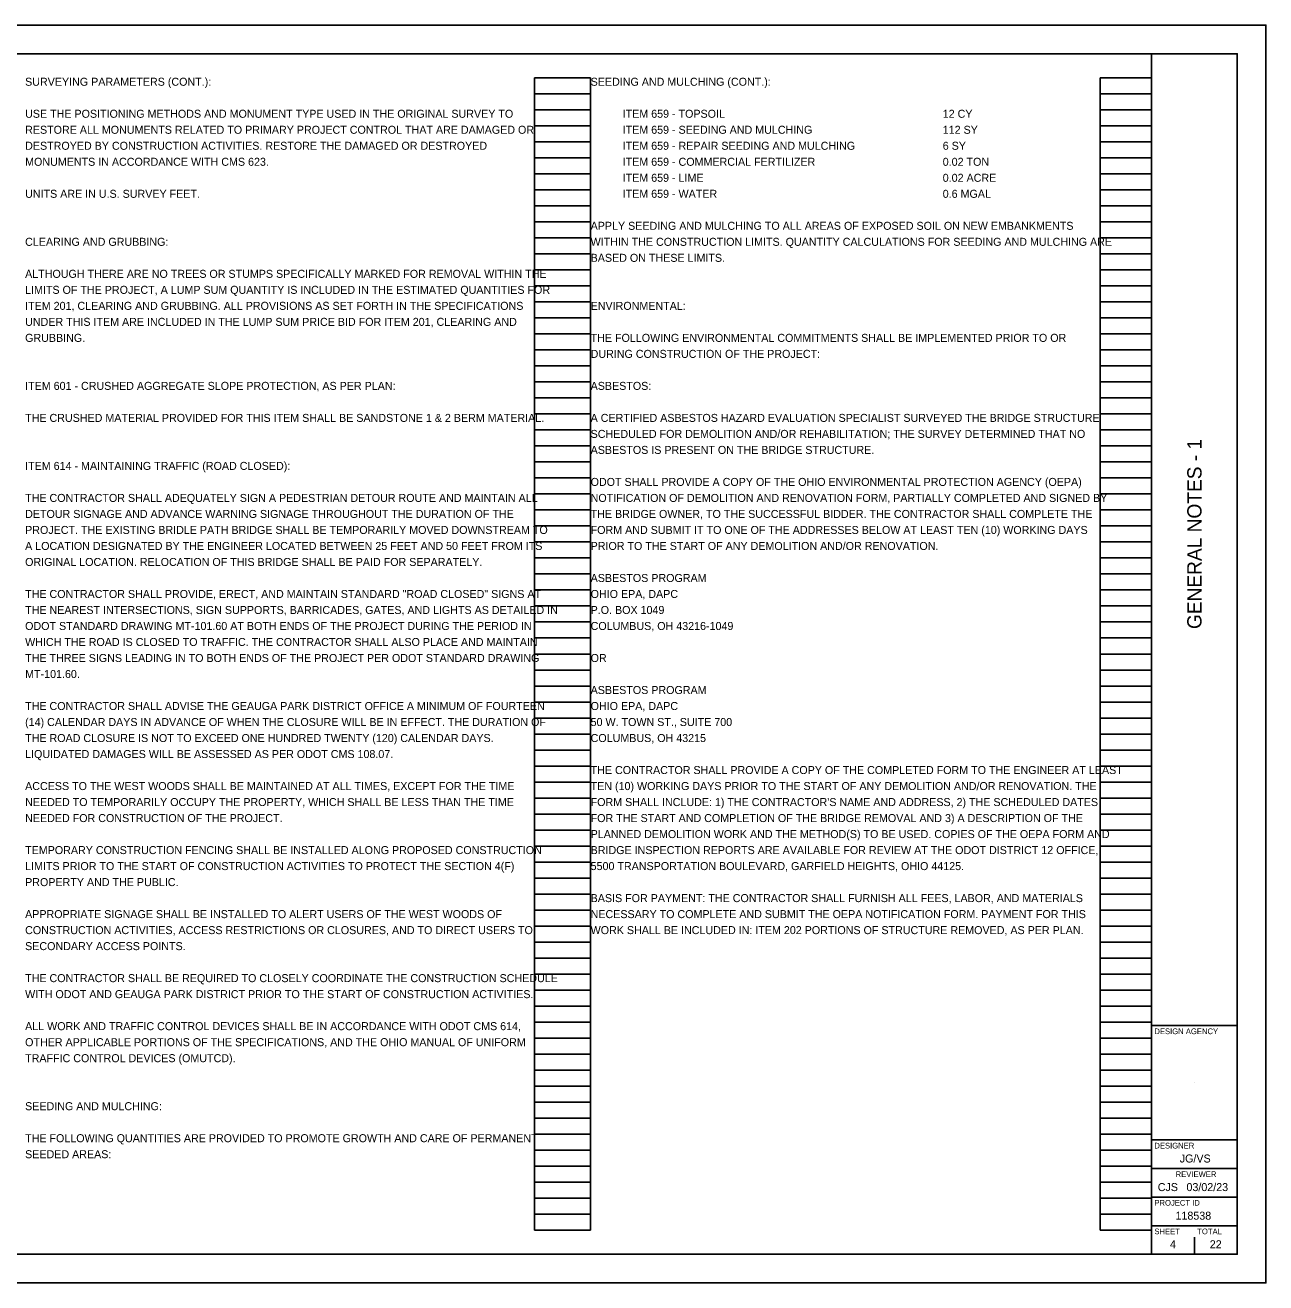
# Model space of a CAD drawing. Extents: x 0 to 34, y -0.1 to 22.
# Drawn here: x 12.29 to 34, y 0 to 22 of the extents above; entities that cross this region are included whole.
import ezdxf

# ---------------------------------------------------------------- set-up
doc = ezdxf.new("R2010")
doc.units = 0
for name, color, linetype in [('SH_Border', 7, 'Continuous'), ('SH_Cut_Line', 7, 'Continuous'), ('SH_Data', 7, 'Continuous'), ('SH_Text', 7, 'Continuous')]:
    doc.layers.add(name, color=color, linetype=linetype)

msp = doc.modelspace()

# ---------------------------------------------------------------- linework, layer by layer
at = {"layer": 'SH_Border'}
for p, q in [((32, 0.5), (32, 21.5)), ((32, 4.5), (33.5, 4.5)), ((32, 2.5), (33.5, 2.5)), ((32, 2), (33.5, 2)), ((32, 1.5), (33.5, 1.5)), ((32, 1), (33.5, 1))]:
    msp.add_line(p, q, dxfattribs=at)
msp.add_lwpolyline([(1.5, 21.5), (33.5, 21.5), (33.5, 0.5), (1.5, 0.5)], close=True, dxfattribs=at)
at = {"layer": 'SH_Cut_Line'}
msp.add_lwpolyline([(0, 0), (34, 0), (34, 22), (0, 22)], close=True, dxfattribs=at)
at = {"layer": 'SH_Data'}
for p, q in [((21.207, 0.92), (21.207, 21.08)), ((21.207, 21.08), (22.187, 21.08)), ((22.187, 0.92), (22.187, 21.08)), ((31.1, 0.92), (31.1, 21.08)), ((31.1, 21.08), (32, 21.08)), ((32, 0.92), (32, 21.08)), ((21.207, 20.8), (22.187, 20.8)), ((31.1, 20.8), (32, 20.8)), ((21.207, 20.52), (22.187, 20.52)), ((31.1, 20.52), (32, 20.52)), ((21.207, 20.24), (22.187, 20.24)), ((31.1, 20.24), (32, 20.24)), ((21.207, 19.96), (22.187, 19.96)), ((31.1, 19.96), (32, 19.96)), ((21.207, 19.68), (22.187, 19.68)), ((31.1, 19.68), (32, 19.68)), ((21.207, 19.4), (22.187, 19.4)), ((31.1, 19.4), (32, 19.4)), ((21.207, 19.12), (22.187, 19.12)), ((31.1, 19.12), (32, 19.12)), ((21.207, 18.84), (22.187, 18.84)), ((31.1, 18.84), (32, 18.84)), ((21.207, 18.56), (22.187, 18.56)), ((31.1, 18.56), (32, 18.56)), ((21.207, 18.28), (22.187, 18.28)), ((31.1, 18.28), (32, 18.28)), ((21.207, 18), (22.187, 18)), ((31.1, 18), (32, 18)), ((21.207, 17.72), (22.187, 17.72)), ((31.1, 17.72), (32, 17.72)), ((21.207, 17.44), (22.187, 17.44)), ((31.1, 17.44), (32, 17.44)), ((21.207, 17.16), (22.187, 17.16)), ((31.1, 17.16), (32, 17.16)), ((21.207, 16.88), (22.187, 16.88)), ((31.1, 16.88), (32, 16.88)), ((21.207, 16.6), (22.187, 16.6)), ((31.1, 16.6), (32, 16.6)), ((21.207, 16.32), (22.187, 16.32)), ((31.1, 16.32), (32, 16.32)), ((21.207, 16.04), (22.187, 16.04)), ((31.1, 16.04), (32, 16.04)), ((21.207, 15.76), (22.187, 15.76)), ((31.1, 15.76), (32, 15.76)), ((21.207, 15.48), (22.187, 15.48)), ((31.1, 15.48), (32, 15.48)), ((21.207, 15.2), (22.187, 15.2)), ((31.1, 15.2), (32, 15.2)), ((21.207, 14.92), (22.187, 14.92)), ((31.1, 14.92), (32, 14.92)), ((21.207, 14.64), (22.187, 14.64)), ((31.1, 14.64), (32, 14.64)), ((21.207, 14.36), (22.187, 14.36)), ((31.1, 14.36), (32, 14.36)), ((21.207, 14.08), (22.187, 14.08)), ((31.1, 14.08), (32, 14.08)), ((21.207, 13.8), (22.187, 13.8)), ((31.1, 13.8), (32, 13.8)), ((21.207, 13.52), (22.187, 13.52)), ((31.1, 13.52), (32, 13.52)), ((21.207, 13.24), (22.187, 13.24)), ((31.1, 13.24), (32, 13.24)), ((21.207, 12.96), (22.187, 12.96)), ((31.1, 12.96), (32, 12.96)), ((21.207, 12.68), (22.187, 12.68)), ((31.1, 12.68), (32, 12.68)), ((21.207, 12.4), (22.187, 12.4)), ((31.1, 12.4), (32, 12.4)), ((21.207, 12.12), (22.187, 12.12)), ((31.1, 12.12), (32, 12.12)), ((21.207, 11.84), (22.187, 11.84)), ((31.1, 11.84), (32, 11.84)), ((21.207, 11.56), (22.187, 11.56)), ((31.1, 11.56), (32, 11.56)), ((21.207, 11.28), (22.187, 11.28)), ((31.1, 11.28), (32, 11.28)), ((21.207, 11), (22.187, 11)), ((31.1, 11), (32, 11)), ((21.207, 10.72), (22.187, 10.72)), ((31.1, 10.72), (32, 10.72)), ((21.207, 10.44), (22.187, 10.44)), ((31.1, 10.44), (32, 10.44)), ((21.207, 10.16), (22.187, 10.16)), ((31.1, 10.16), (32, 10.16)), ((21.207, 9.88), (22.187, 9.88)), ((31.1, 9.88), (32, 9.88)), ((21.207, 9.6), (22.187, 9.6)), ((31.1, 9.6), (32, 9.6)), ((21.207, 9.32), (22.187, 9.32)), ((31.1, 9.32), (32, 9.32)), ((21.207, 9.04), (22.187, 9.04)), ((31.1, 9.04), (32, 9.04)), ((21.207, 8.76), (22.187, 8.76)), ((31.1, 8.76), (32, 8.76)), ((21.207, 8.48), (22.187, 8.48)), ((31.1, 8.48), (32, 8.48)), ((21.207, 8.2), (22.187, 8.2)), ((31.1, 8.2), (32, 8.2)), ((21.207, 7.92), (22.187, 7.92)), ((31.1, 7.92), (32, 7.92)), ((21.207, 7.64), (22.187, 7.64)), ((31.1, 7.64), (32, 7.64)), ((21.207, 7.36), (22.187, 7.36)), ((31.1, 7.36), (32, 7.36)), ((21.207, 7.08), (22.187, 7.08)), ((31.1, 7.08), (32, 7.08)), ((21.207, 6.8), (22.187, 6.8)), ((31.1, 6.8), (32, 6.8)), ((21.207, 6.52), (22.187, 6.52)), ((31.1, 6.52), (32, 6.52)), ((21.207, 6.24), (22.187, 6.24)), ((31.1, 6.24), (32, 6.24)), ((21.207, 5.96), (22.187, 5.96)), ((31.1, 5.96), (32, 5.96)), ((21.207, 5.68), (22.187, 5.68)), ((31.1, 5.68), (32, 5.68)), ((21.207, 5.4), (22.187, 5.4)), ((31.1, 5.4), (32, 5.4)), ((21.207, 5.12), (22.187, 5.12)), ((31.1, 5.12), (32, 5.12)), ((21.207, 4.84), (22.187, 4.84)), ((31.1, 4.84), (32, 4.84)), ((21.207, 4.56), (22.187, 4.56)), ((31.1, 4.56), (32, 4.56)), ((21.207, 4.28), (22.187, 4.28)), ((31.1, 4.28), (32, 4.28)), ((21.207, 4), (22.187, 4)), ((31.1, 4), (32, 4)), ((21.207, 3.72), (22.187, 3.72)), ((31.1, 3.72), (32, 3.72)), ((21.207, 3.44), (22.187, 3.44)), ((31.1, 3.44), (32, 3.44)), ((32.75, 3.5), (32.75, 3.5)), ((21.207, 3.16), (22.187, 3.16)), ((31.1, 3.16), (32, 3.16)), ((21.207, 2.88), (22.187, 2.88)), ((31.1, 2.88), (32, 2.88)), ((21.207, 2.6), (22.187, 2.6)), ((31.1, 2.6), (32, 2.6)), ((21.207, 2.32), (22.187, 2.32)), ((31.1, 2.32), (32, 2.32)), ((21.207, 2.04), (22.187, 2.04)), ((31.1, 2.04), (32, 2.04)), ((21.207, 1.76), (22.187, 1.76)), ((31.1, 1.76), (32, 1.76)), ((21.207, 1.48), (22.187, 1.48)), ((31.1, 1.48), (32, 1.48)), ((21.207, 1.2), (22.187, 1.2)), ((31.1, 1.2), (32, 1.2)), ((21.207, 0.92), (22.187, 0.92)), ((31.1, 0.92), (32, 0.92)), ((32.375, 0.675), (32.375, 0.675)), ((32.75, 0.5), (32.75, 0.8))]:
    msp.add_line(p, q, dxfattribs=at)

# ---------------------------------------------------------------- texts
msp.add_text('GENERAL NOTES - 1', height=0.25, rotation=90, dxfattribs=at).set_placement((32.875, 11.437))
for s, height, p in [('DESIGN AGENCY', 0.1, (32.05, 4.35)), ('DESIGNER', 0.1, (32.05, 2.35)), ('JG/VS', 0.14, (32.494, 2.105)), ('REVIEWER', 0.1, (32.422, 1.85)), ('CJS', 0.14, (32.109, 1.605)), ('03/02/23', 0.14, (32.611, 1.605)), ('PROJECT ID', 0.1, (32.05, 1.35)), ('118538', 0.14, (32.419, 1.105)), ('SHEET', 0.1, (32.05, 0.85)), ('TOTAL', 0.1, (32.8, 0.85)), ('4', 0.14, (32.322, 0.605)), ('22', 0.14, (33.019, 0.605))]:
    msp.add_text(s, height=height, dxfattribs=at).set_placement(p)
at = {"layer": 'SH_Text'}
for s, p in [('SURVEYING PARAMETERS (CONT.):', (12.293, 20.94)), ('SEEDING AND MULCHING (CONT.):', (22.187, 20.94)), ('USE THE POSITIONING METHODS AND MONUMENT TYPE USED IN THE ORIGINAL SURVEY TO ', (12.293, 20.38)), ('ITEM 659 - TOPSOIL', (22.747, 20.38)), ('12 CY', (28.347, 20.38)), ('RESTORE ALL MONUMENTS RELATED TO PRIMARY PROJECT CONTROL THAT ARE DAMAGED OR', (12.293, 20.1)), ('ITEM 659 - SEEDING AND MULCHING', (22.747, 20.1)), ('112 SY', (28.347, 20.1)), ('DESTROYED BY CONSTRUCTION ACTIVITIES. RESTORE THE DAMAGED OR DESTROYED ', (12.293, 19.82)), ('ITEM 659 - REPAIR SEEDING AND MULCHING', (22.747, 19.82)), ('6 SY', (28.347, 19.82)), ('MONUMENTS IN ACCORDANCE WITH CMS 623.', (12.293, 19.54)), ('ITEM 659 - COMMERCIAL FERTILIZER', (22.747, 19.54)), ('0.02 TON', (28.347, 19.54)), ('ITEM 659 - LIME', (22.747, 19.26)), ('0.02 ACRE', (28.347, 19.26)), ('UNITS ARE IN U.S. SURVEY FEET.', (12.293, 18.98)), ('ITEM 659 - WATER', (22.747, 18.98)), ('0.6 MGAL', (28.347, 18.98)), ('APPLY SEEDING AND MULCHING TO ALL AREAS OF EXPOSED SOIL ON NEW EMBANKMENTS ', (22.187, 18.42)), ('CLEARING AND GRUBBING:', (12.293, 18.14)), ('WITHIN THE CONSTRUCTION LIMITS. QUANTITY CALCULATIONS FOR SEEDING AND MULCHING ARE ', (22.187, 18.14)), ('BASED ON THESE LIMITS.', (22.187, 17.86)), ('ALTHOUGH THERE ARE NO TREES OR STUMPS SPECIFICALLY MARKED FOR REMOVAL WITHIN THE ', (12.293, 17.58)), ('LIMITS OF THE PROJECT, A LUMP SUM QUANTITY IS INCLUDED IN THE ESTIMATED QUANTITIES FOR ', (12.293, 17.3)), ('ITEM 201, CLEARING AND GRUBBING. ALL PROVISIONS AS SET FORTH IN THE SPECIFICATIONS ', (12.293, 17.02)), ('ENVIRONMENTAL:', (22.187, 17.02)), ('UNDER THIS ITEM ARE INCLUDED IN THE LUMP SUM PRICE BID FOR ITEM 201, CLEARING AND ', (12.293, 16.74)), ('GRUBBING.', (12.293, 16.46)), ('THE FOLLOWING ENVIRONMENTAL COMMITMENTS SHALL BE IMPLEMENTED PRIOR TO OR ', (22.187, 16.46)), ('DURING CONSTRUCTION OF THE PROJECT:', (22.187, 16.18)), ('ITEM 601 - CRUSHED AGGREGATE SLOPE PROTECTION, AS PER PLAN:', (12.293, 15.62)), ('ASBESTOS:', (22.187, 15.62)), ('THE CRUSHED MATERIAL PROVIDED FOR THIS ITEM SHALL BE SANDSTONE 1 & 2 BERM MATERIAL.', (12.293, 15.06)), ('A CERTIFIED ASBESTOS HAZARD EVALUATION SPECIALIST SURVEYED THE BRIDGE STRUCTURE ', (22.187, 15.06)), ('SCHEDULED FOR DEMOLITION AND/OR REHABILITATION; THE SURVEY DETERMINED THAT NO ', (22.187, 14.78)), ('ASBESTOS IS PRESENT ON THE BRIDGE STRUCTURE.', (22.187, 14.5)), ('ITEM 614 - MAINTAINING TRAFFIC (ROAD CLOSED):', (12.293, 14.22)), ('ODOT SHALL PROVIDE A COPY OF THE OHIO ENVIRONMENTAL PROTECTION AGENCY (OEPA) ', (22.187, 13.94)), ('THE CONTRACTOR SHALL ADEQUATELY SIGN A PEDESTRIAN DETOUR ROUTE AND MAINTAIN ALL ', (12.293, 13.66)), ('NOTIFICATION OF DEMOLITION AND RENOVATION FORM, PARTIALLY COMPLETED AND SIGNED BY ', (22.187, 13.66)), ('DETOUR SIGNAGE AND ADVANCE WARNING SIGNAGE THROUGHOUT THE DURATION OF THE ', (12.293, 13.38)), ('THE BRIDGE OWNER, TO THE SUCCESSFUL BIDDER. THE CONTRACTOR SHALL COMPLETE THE ', (22.187, 13.38)), ('PROJECT. THE EXISTING BRIDLE PATH BRIDGE SHALL BE TEMPORARILY MOVED DOWNSTREAM TO ', (12.293, 13.1)), ('FORM AND SUBMIT IT TO ONE OF THE ADDRESSES BELOW AT LEAST TEN (10) WORKING DAYS ', (22.187, 13.1)), ('A LOCATION DESIGNATED BY THE ENGINEER LOCATED BETWEEN 25 FEET AND 50 FEET FROM ITS ', (12.293, 12.82)), ('PRIOR TO THE START OF ANY DEMOLITION AND/OR RENOVATION.', (22.187, 12.82)), ('ORIGINAL LOCATION. RELOCATION OF THIS BRIDGE SHALL BE PAID FOR SEPARATELY.', (12.293, 12.54)), ('ASBESTOS PROGRAM', (22.187, 12.26)), ('THE CONTRACTOR SHALL PROVIDE, ERECT, AND MAINTAIN STANDARD "ROAD CLOSED" SIGNS AT ', (12.293, 11.98)), ('OHIO EPA, DAPC', (22.187, 11.98)), ('THE NEAREST INTERSECTIONS, SIGN SUPPORTS, BARRICADES, GATES, AND LIGHTS AS DETAILED IN ', (12.293, 11.7)), ('P.O. BOX 1049', (22.187, 11.7)), ('ODOT STANDARD DRAWING MT-101.60 AT BOTH ENDS OF THE PROJECT DURING THE PERIOD IN ', (12.293, 11.42)), ('COLUMBUS, OH 43216-1049', (22.187, 11.42)), ('WHICH THE ROAD IS CLOSED TO TRAFFIC. THE CONTRACTOR SHALL ALSO PLACE AND MAINTAIN ', (12.293, 11.14)), ('THE THREE SIGNS LEADING IN TO BOTH ENDS OF THE PROJECT PER ODOT STANDARD DRAWING ', (12.293, 10.86)), ('OR', (22.187, 10.86)), ('MT-101.60.', (12.293, 10.58)), ('ASBESTOS PROGRAM', (22.187, 10.3)), ('THE CONTRACTOR SHALL ADVISE THE GEAUGA PARK DISTRICT OFFICE A MINIMUM OF FOURTEEN ', (12.293, 10.02)), ('OHIO EPA, DAPC', (22.187, 10.02)), ('(14) CALENDAR DAYS IN ADVANCE OF WHEN THE CLOSURE WILL BE IN EFFECT. THE DURATION OF ', (12.293, 9.74)), ('50 W. TOWN ST., SUITE 700', (22.187, 9.74)), ('THE ROAD CLOSURE IS NOT TO EXCEED ONE HUNDRED TWENTY (120) CALENDAR DAYS. ', (12.293, 9.46)), ('COLUMBUS, OH 43215', (22.187, 9.46)), ('LIQUIDATED DAMAGES WILL BE ASSESSED AS PER ODOT CMS 108.07.', (12.293, 9.18)), ('THE CONTRACTOR SHALL PROVIDE A COPY OF THE COMPLETED FORM TO THE ENGINEER AT LEAST ', (22.187, 8.9)), ('ACCESS TO THE WEST WOODS SHALL BE MAINTAINED AT ALL TIMES, EXCEPT FOR THE TIME ', (12.293, 8.62)), ('TEN (10) WORKING DAYS PRIOR TO THE START OF ANY DEMOLITION AND/OR RENOVATION. THE ', (22.187, 8.62)), ('NEEDED TO TEMPORARILY OCCUPY THE PROPERTY, WHICH SHALL BE LESS THAN THE TIME ', (12.293, 8.34)), ("FORM SHALL INCLUDE: 1) THE CONTRACTOR'S NAME AND ADDRESS, 2) THE SCHEDULED DATES ", (22.187, 8.34)), ('NEEDED FOR CONSTRUCTION OF THE PROJECT.', (12.293, 8.06)), ('FOR THE START AND COMPLETION OF THE BRIDGE REMOVAL AND 3) A DESCRIPTION OF THE ', (22.187, 8.06)), ('PLANNED DEMOLITION WORK AND THE METHOD(S) TO BE USED. COPIES OF THE OEPA FORM AND ', (22.187, 7.78)), ('TEMPORARY CONSTRUCTION FENCING SHALL BE INSTALLED ALONG PROPOSED CONSTRUCTION ', (12.293, 7.5)), ('BRIDGE INSPECTION REPORTS ARE AVAILABLE FOR REVIEW AT THE ODOT DISTRICT 12 OFFICE, ', (22.187, 7.5)), ('LIMITS PRIOR TO THE START OF CONSTRUCTION ACTIVITIES TO PROTECT THE SECTION 4(F) ', (12.293, 7.22)), ('5500 TRANSPORTATION BOULEVARD, GARFIELD HEIGHTS, OHIO 44125.', (22.187, 7.22)), ('PROPERTY AND THE PUBLIC.', (12.293, 6.94)), ('BASIS FOR PAYMENT: THE CONTRACTOR SHALL FURNISH ALL FEES, LABOR, AND MATERIALS ', (22.187, 6.66)), ('APPROPRIATE SIGNAGE SHALL BE INSTALLED TO ALERT USERS OF THE WEST WOODS OF ', (12.293, 6.38)), ('NECESSARY TO COMPLETE AND SUBMIT THE OEPA NOTIFICATION FORM. PAYMENT FOR THIS ', (22.187, 6.38)), ('CONSTRUCTION ACTIVITIES, ACCESS RESTRICTIONS OR CLOSURES, AND TO DIRECT USERS TO ', (12.293, 6.1)), ('WORK SHALL BE INCLUDED IN: ITEM 202 PORTIONS OF STRUCTURE REMOVED, AS PER PLAN.', (22.187, 6.1)), ('SECONDARY ACCESS POINTS.', (12.293, 5.82)), ('THE CONTRACTOR SHALL BE REQUIRED TO CLOSELY COORDINATE THE CONSTRUCTION SCHEDULE ', (12.293, 5.26)), ('WITH ODOT AND GEAUGA PARK DISTRICT PRIOR TO THE START OF CONSTRUCTION ACTIVITIES.', (12.293, 4.98)), ('ALL WORK AND TRAFFIC CONTROL DEVICES SHALL BE IN ACCORDANCE WITH ODOT CMS 614, ', (12.293, 4.42)), ('OTHER APPLICABLE PORTIONS OF THE SPECIFICATIONS, AND THE OHIO MANUAL OF UNIFORM ', (12.293, 4.14)), ('TRAFFIC CONTROL DEVICES (OMUTCD).', (12.293, 3.86)), ('SEEDING AND MULCHING:', (12.293, 3.02)), ('THE FOLLOWING QUANTITIES ARE PROVIDED TO PROMOTE GROWTH AND CARE OF PERMANENT ', (12.293, 2.46)), ('SEEDED AREAS:', (12.293, 2.18))]:
    msp.add_text(s, height=0.14, dxfattribs=at).set_placement(p)

doc.saveas('drawing.dxf')
